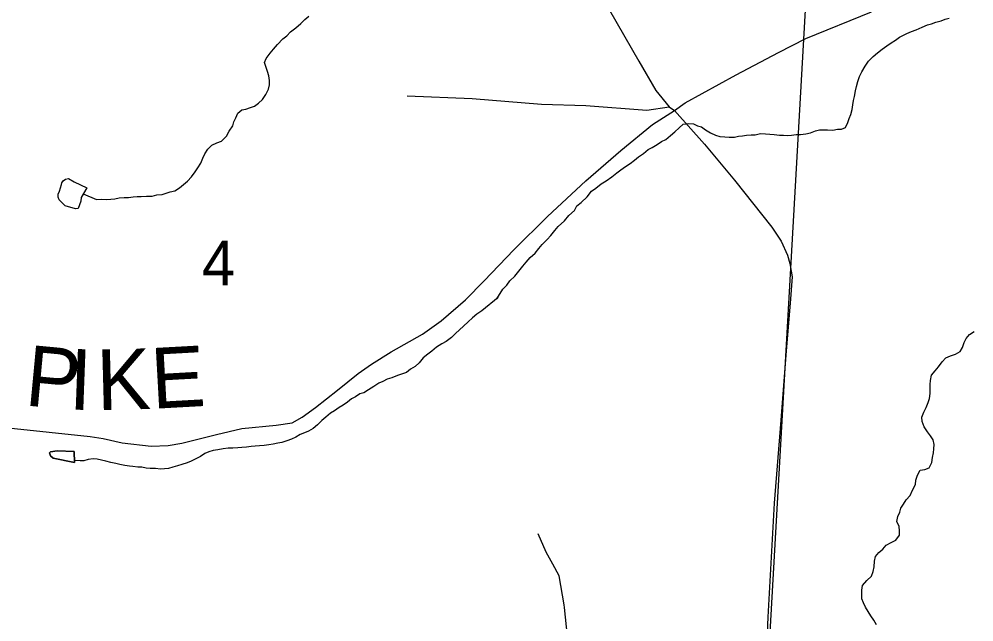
# Model space of a CAD drawing. Extents: x -20.2 to 34, y 0 to 22.
# Drawn here: x 7.17 to 8.064, y 16.071 to 16.636 of the extents above; entities that cross this region are included whole.
import ezdxf

# ---------------------------------------------------------------- set-up
doc = ezdxf.new("R2010")
doc.units = 0
for name, color, linetype in [('Default', 7, 'Continuous'), ('GM_X_County_Road', 7, 'Continuous'), ('GM_X_County_Road_Text', 7, 'Continuous'), ('GM_X_Minor_River', 7, 'Continuous'), ('GM_X_Section', 7, 'Continuous'), ('GM_X_Section_Text', 7, 'Continuous'), ('GM_X_Township_Road', 7, 'Continuous')]:
    doc.layers.add(name, color=color, linetype=linetype)

msp = doc.modelspace()

# ---------------------------------------------------------------- linework, layer by layer
at = {"layer": 'Default'}
msp.add_lwpolyline([(8.9, 15.82114), (8.9, 16.85373), (7.92004, 16.89751), (7.86237, 15.87982)], close=True, dxfattribs=at)
at = {"layer": 'GM_X_County_Road'}
for points in [[(7.72235, 16.64406), (7.74979, 16.59622), (7.76587, 16.56877), (7.77842, 16.55348), (7.78325, 16.55004), (7.81138, 16.51861), (7.83946, 16.48482), (7.87425, 16.44084), (7.88306, 16.42755), (7.88916, 16.41449), (7.89115, 16.40679), (7.89348, 16.39432), (7.8919, 16.37374), (7.88742, 16.32081), (7.88295, 16.25992), (7.87649, 16.18239), (7.87077, 16.07553), (7.86729, 15.99502), (7.86365, 15.95491), (7.86343, 15.94985), (7.86231, 15.93518)], [(7.78325, 16.55004), (7.79334, 16.55732), (7.84088, 16.5835), (7.8805, 16.60439), (7.90619, 16.61759), (7.96766, 16.64232)], [(7.15949, 16.25286), (7.23635, 16.24476), (7.24827, 16.24277), (7.26628, 16.23885), (7.2935, 16.23557), (7.30941, 16.23632), (7.32221, 16.23855), (7.35439, 16.2466), (7.37824, 16.25222), (7.4103, 16.25545), (7.42521, 16.25744), (7.43465, 16.26291), (7.44708, 16.27185), (7.4677, 16.288), (7.48726, 16.30372), (7.49976, 16.3126), (7.51815, 16.32404), (7.54722, 16.34069), (7.56487, 16.35311), (7.58773, 16.37275), (7.60512, 16.39064), (7.63295, 16.41971), (7.66451, 16.45077), (7.7003, 16.48407), (7.7331, 16.51265), (7.76267, 16.53701), (7.78325, 16.55004)]]:
    msp.add_lwpolyline(points, dxfattribs=at)
at = {"layer": 'GM_X_Minor_River'}
for points in [[(7.22974, 16.47184), (7.24225, 16.4668), (7.24718, 16.46686), (7.25136, 16.46654), (7.25553, 16.46697), (7.25932, 16.46739), (7.26349, 16.46821), (7.26804, 16.46864), (7.27221, 16.4687), (7.27639, 16.46913), (7.28017, 16.46956), (7.28397, 16.4696), (7.28891, 16.46967), (7.29422, 16.46973), (7.29876, 16.47093), (7.30369, 16.47137), (7.30747, 16.47256), (7.31125, 16.47375), (7.31542, 16.47493), (7.31994, 16.47765), (7.3237, 16.48074), (7.32746, 16.48382), (7.33121, 16.48805), (7.33457, 16.49265), (7.33718, 16.49648), (7.33979, 16.50069), (7.34164, 16.50527), (7.34348, 16.50947), (7.34647, 16.51368), (7.35022, 16.51753), (7.35475, 16.51987), (7.35929, 16.52144), (7.36379, 16.52606), (7.36639, 16.53065), (7.36975, 16.53563), (7.37084, 16.53944), (7.3727, 16.54326), (7.37455, 16.54746), (7.37831, 16.55054), (7.38209, 16.55135), (7.38625, 16.55292), (7.39003, 16.55411), (7.3938, 16.55682), (7.39755, 16.56028), (7.40054, 16.56488), (7.40314, 16.56985), (7.40422, 16.57404), (7.40417, 16.57821), (7.40337, 16.58238), (7.40218, 16.58654), (7.40061, 16.59108), (7.39942, 16.59486), (7.4009, 16.59868), (7.40464, 16.60367), (7.40801, 16.60751), (7.41176, 16.61173), (7.41663, 16.61711), (7.42039, 16.61982), (7.42376, 16.62366), (7.42865, 16.62752), (7.43354, 16.63137), (7.43729, 16.63522), (7.44106, 16.63831)], [(8.00076, 16.62217), (8.00529, 16.62412), (8.00945, 16.62569), (8.01511, 16.62804), (8.02002, 16.63038), (8.02381, 16.63119), (8.02797, 16.63276), (8.03289, 16.63396), (8.03667, 16.63553), (8.04045, 16.63634)], [(7.61691, 16.37377), (7.62244, 16.3827), (7.62619, 16.38655), (7.62919, 16.39038), (7.63369, 16.395), (7.63743, 16.3996), (7.64117, 16.4042), (7.64454, 16.40804), (7.64829, 16.41227), (7.6528, 16.4165), (7.65616, 16.42072), (7.65953, 16.42456), (7.66404, 16.42918), (7.66741, 16.43302), (7.67115, 16.43762), (7.67452, 16.44146), (7.68015, 16.44685), (7.68427, 16.45184), (7.68953, 16.45646), (7.69176, 16.46067), (7.6959, 16.46376), (7.70153, 16.46915), (7.70564, 16.47452), (7.70979, 16.47722), (7.71467, 16.48146), (7.71919, 16.48418), (7.72446, 16.48804), (7.72936, 16.49152), (7.73312, 16.49461), (7.73726, 16.4977), (7.74178, 16.50041), (7.74592, 16.50351), (7.74968, 16.50659), (7.7542, 16.50969), (7.75871, 16.51354), (7.76248, 16.51549), (7.76701, 16.5182), (7.77115, 16.52091), (7.7753, 16.52286), (7.77943, 16.52671), (7.78357, 16.53018), (7.7877, 16.53365), (7.79146, 16.53712), (7.79638, 16.53794), (7.80094, 16.53762), (7.80476, 16.53577), (7.80857, 16.53468), (7.81239, 16.53207), (7.81699, 16.52908), (7.82157, 16.52686), (7.82575, 16.52578), (7.83031, 16.52545), (7.83449, 16.52513), (7.83942, 16.52519), (7.84321, 16.526), (7.847, 16.52642), (7.85079, 16.52685), (7.85496, 16.52728), (7.85876, 16.52733), (7.86368, 16.52853), (7.86862, 16.52821), (7.87242, 16.52788), (7.8766, 16.52755), (7.88154, 16.52686), (7.88534, 16.5269), (7.88914, 16.52657), (7.89293, 16.527), (7.8971, 16.52743), (7.90127, 16.52748), (7.9062, 16.52831), (7.91074, 16.52912), (7.91528, 16.53108), (7.91906, 16.53188), (7.92286, 16.53193), (7.92665, 16.53198), (7.93159, 16.53166), (7.93576, 16.53247), (7.93955, 16.53252), (7.94333, 16.53409), (7.94556, 16.53867), (7.94665, 16.54249), (7.9485, 16.54631), (7.94959, 16.55088), (7.95029, 16.55544), (7.95101, 16.55925), (7.95172, 16.56306), (7.9528, 16.56839), (7.95351, 16.57258), (7.95497, 16.57715), (7.95644, 16.58173), (7.95866, 16.58631), (7.96164, 16.59167), (7.965, 16.59627), (7.96913, 16.6005), (7.97326, 16.60397), (7.97778, 16.60744), (7.98192, 16.61053), (7.98606, 16.61325), (7.9902, 16.61596), (7.99397, 16.61866), (8.00076, 16.62217)], [(7.23304, 16.4775), (7.2278, 16.46852), (7.22746, 16.4651), (7.22489, 16.45823), (7.22262, 16.45782), (7.21271, 16.46073), (7.20926, 16.46411), (7.20733, 16.46636), (7.20616, 16.46901), (7.20613, 16.47167), (7.20762, 16.47434), (7.20944, 16.48082), (7.2098, 16.48235), (7.21092, 16.48426), (7.21318, 16.48581), (7.21583, 16.48622), (7.22118, 16.48325), (7.23304, 16.4775)], [(7.6183, 16.37488), (7.60282, 16.3625), (7.59828, 16.35943), (7.59413, 16.35598), (7.58998, 16.35216), (7.58584, 16.34795), (7.58207, 16.34451), (7.57829, 16.34106), (7.57452, 16.33762), (7.56961, 16.33378), (7.56545, 16.33147), (7.56054, 16.3284), (7.55601, 16.32457), (7.55223, 16.32189), (7.54808, 16.31844), (7.54432, 16.31386), (7.54054, 16.31041), (7.53601, 16.30772), (7.53223, 16.30466), (7.52769, 16.3031), (7.5239, 16.30194), (7.5186, 16.29962), (7.51443, 16.29845), (7.51027, 16.29614), (7.50649, 16.2946), (7.50195, 16.29153), (7.49666, 16.28845), (7.4925, 16.28576), (7.48871, 16.2846), (7.48455, 16.28191), (7.48077, 16.27998), (7.477, 16.27692), (7.47322, 16.27423), (7.46944, 16.27193), (7.46491, 16.26886), (7.46112, 16.26655), (7.45698, 16.26272), (7.4532, 16.25966), (7.44905, 16.25583), (7.4449, 16.25239), (7.44074, 16.2497), (7.43696, 16.24815), (7.43279, 16.2466), (7.42863, 16.24429), (7.42485, 16.24237), (7.4203, 16.24082), (7.41576, 16.23927), (7.41197, 16.23848), (7.40741, 16.23769), (7.40362, 16.2369), (7.39907, 16.23649), (7.3949, 16.23608), (7.39072, 16.23567), (7.38693, 16.23526), (7.38275, 16.23485), (7.3782, 16.23444), (7.37441, 16.23403), (7.36985, 16.234), (7.36529, 16.23397), (7.36074, 16.23318), (7.35581, 16.23238), (7.35126, 16.23159), (7.34747, 16.23042), (7.34369, 16.22888), (7.33953, 16.22619), (7.33574, 16.22426), (7.33083, 16.22157), (7.32704, 16.22002), (7.32212, 16.21847), (7.31795, 16.2173), (7.31378, 16.21613), (7.30961, 16.21496), (7.30582, 16.21456), (7.30203, 16.21415), (7.29746, 16.21488), (7.29253, 16.21484), (7.28873, 16.21519), (7.28455, 16.21592), (7.28075, 16.2159), (7.27619, 16.21662), (7.27304, 16.21704), (7.26858, 16.21771), (7.26402, 16.21843), (7.26017, 16.2194), (7.25565, 16.22027), (7.25085, 16.22165), (7.2469, 16.22249), (7.24272, 16.2236), (7.23916, 16.22389), (7.23437, 16.22316), (7.23018, 16.22212), (7.22678, 16.22196), (7.22146, 16.22237)], [(7.97253, 16.06855), (7.96984, 16.07271), (7.96715, 16.07687), (7.96447, 16.08103), (7.96216, 16.08481), (7.96023, 16.08897), (7.95868, 16.09276), (7.95866, 16.09656), (7.95863, 16.10074), (7.95935, 16.1053), (7.96349, 16.10988), (7.96764, 16.11409), (7.96913, 16.11828), (7.97024, 16.12285), (7.97058, 16.12816), (7.97131, 16.13235), (7.9747, 16.13617), (7.97847, 16.13923), (7.98148, 16.14305), (7.98602, 16.14536), (7.99056, 16.14768), (7.99394, 16.15226), (7.99391, 16.15643), (7.9935, 16.16061), (7.99157, 16.16515), (7.9923, 16.16971), (7.99417, 16.1739), (7.99528, 16.17771), (7.99753, 16.18152), (8.00016, 16.18534), (8.00392, 16.18954), (8.00617, 16.1945), (8.00878, 16.19983), (8.00914, 16.20401), (8.01062, 16.20858), (8.01324, 16.21316), (8.01779, 16.21395), (8.02158, 16.21549), (8.0242, 16.22045), (8.02493, 16.22501), (8.02565, 16.22957), (8.02601, 16.23337), (8.02636, 16.23718), (8.02557, 16.24173), (8.02288, 16.2455), (8.02019, 16.24928), (8.01712, 16.25382), (8.01519, 16.25874), (8.01478, 16.26292), (8.01664, 16.26749), (8.01889, 16.27206), (8.02075, 16.27663), (8.02186, 16.28043), (8.02259, 16.285), (8.02256, 16.28955), (8.02253, 16.29335), (8.02288, 16.29715), (8.02398, 16.3021), (8.02737, 16.3063), (8.03038, 16.31012), (8.03377, 16.3147), (8.03715, 16.31852), (8.0417, 16.32045), (8.04624, 16.322), (8.05078, 16.32432), (8.05303, 16.32813), (8.05452, 16.3327), (8.05639, 16.33651), (8.0594, 16.34033), (8.06393, 16.34302)], [(7.22141, 16.2306), (7.20545, 16.2313), (7.199, 16.2305), (7.19825, 16.22936), (7.19865, 16.22746)], [(7.22141, 16.2306), (7.22148, 16.22041), (7.2017, 16.22444), (7.19903, 16.2267), (7.19865, 16.22746), (7.19825, 16.22936), (7.199, 16.2305), (7.20545, 16.2313), (7.22141, 16.2306)], [(7.19865, 16.22746), (7.19903, 16.2267), (7.2017, 16.22444), (7.22148, 16.22041), (7.22141, 16.2306)]]:
    msp.add_lwpolyline(points, dxfattribs=at)
at = {"layer": 'GM_X_Section'}
msp.add_lwpolyline([(6.85272, 16.95336), (7.92004, 16.89751), (7.86237, 15.87982), (6.79044, 15.94473), (6.80008, 16.11433), (6.82053, 16.44033)], close=True, dxfattribs=at)
at = {"layer": 'GM_X_Township_Road'}
for points in [[(7.53293, 16.56367), (7.59378, 16.56124), (7.65882, 16.55583), (7.70038, 16.55465), (7.75725, 16.55034), (7.77842, 16.55348)], [(7.68018, 16.0845), (7.67987, 16.08728), (7.67521, 16.11425), (7.6695, 16.12514), (7.66328, 16.13656), (7.65579, 16.15378)], [(7.86365, 15.95491), (7.84666, 15.95575), (7.83772, 15.95501), (7.82878, 15.95451), (7.79546, 15.95276), (7.77144, 15.95058), (7.74928, 15.95005), (7.73931, 15.94954), (7.72043, 15.9478), (7.7123, 15.94773), (7.70254, 15.95103), (7.69309, 15.95725), (7.68688, 15.96197), (7.6762, 15.97042), (7.66949, 15.97986), (7.667, 15.98707), (7.66899, 15.99378), (7.67595, 16.00496), (7.6804, 16.01569), (7.68365, 16.03006), (7.68415, 16.04845), (7.68018, 16.0845)]]:
    msp.add_lwpolyline(points, dxfattribs=at)

# ---------------------------------------------------------------- texts
at = {"layer": 'GM_X_County_Road_Text'}
for s, rotation, p in [('P', 354.62791, (7.17407, 16.27397)), ('I', 357.89531, (7.2157, 16.27016)), ('K', 1.49494, (7.24285, 16.26928)), ('E', 3.1675, (7.29462, 16.27065))]:
    msp.add_text(s, height=0.05682, rotation=rotation, dxfattribs=at).set_placement(p)
at = {"layer": 'GM_X_Section_Text'}
msp.add_text('4', height=0.04186, rotation=0.00001, dxfattribs=at).set_placement((7.34083, 16.3863))

doc.saveas('drawing.dxf')
